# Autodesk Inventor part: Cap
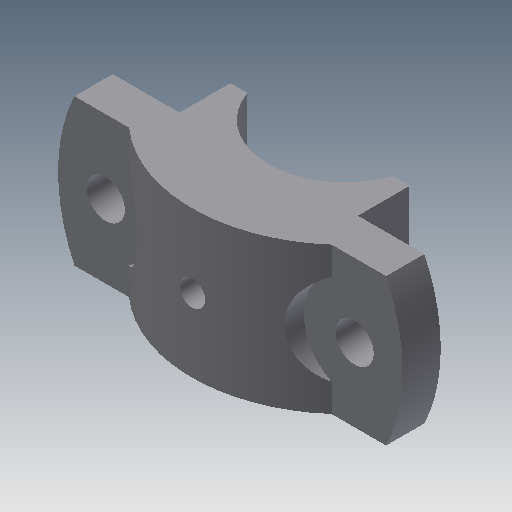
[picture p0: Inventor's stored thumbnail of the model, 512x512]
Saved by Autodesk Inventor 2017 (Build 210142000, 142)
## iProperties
Created: 2009-04
Part Number: Cap
Document SubType Name: Modeling
Designer: Sham
Density: 1 g/cm^3
Material: Generic
Appearance: Default
Author: Sham
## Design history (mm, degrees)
sketch "Sketch1"
  geometry: L1 (-48.857, 23)-(48.857, 23); L2 (48.857, -23)-(-48.857, -23); A1 r 54 centre (0, 0) between (-48.857, 23) and (-48.857, -23); A2 r 54 centre (0, 0) between (48.857, -23) and (48.857, 23); 1 further point
  constraints: 4 end point, 4 point on circle, 2 centre point, 2 coincident, 1 horizontal, 1 parallel, 1 other
  dimensions: "d3" = 54 radius of A1; "d4" = 54 radius of A2; "d5" = 46 distance between parallel lines of L2 L1; "d6" = 23 distance from line of point (0, 0) L1
extrude "Extrusion1" new body sketch "Sketch1" distance "d7" = 12; taper "d8" = 0 deg
sketch "Sketch3"
  geometry: L1 (20.906, 0)-(20.906, -16); L2 (76.906, -0.137)-(76.906, -16.137); L3 (20.906, -16)-(26.23, -16); L4 (71.532, -16.137)-(76.906, -16.137); L5 (76.906, -0.137)-(76.857, 12); L6 (97.714, 0)-(0, 0) reference; L7 (76.857, 12)-(80.606, 12); L8 (17.108, 12)-(20.906, 12); L9 (20.906, 12)-(20.906, 0); L10 (0, 12)-(97.714, 12) reference; A1 r 24 centre (48.857, -24) between (71.532, -16.137) and (26.23, -16); A2 r 48 centre (48.857, -24) between (80.606, 12) and (17.108, 12); 3 further points
  constraints: 16 end point, 4 point on circle, 3 parallel, 3 perpendicular, 2 centre point, 2 coincident, 2 vertical alignment, 1 collinear, 1 midpoint, 1 vertical, 2 other
  dimensions: "d17" = 48 diameter of A1; "d18" = 16 distance of L1.start L1.end; "d19" = 56 distance between parallel lines of L2 L1; "d21" = 8 vertical distance of A1.centre L1.end; "d22" = 48 radius of A2; "d23" = 0 distance from line of L6 L1.start; "d38" = 31.74902 distance of L7.end point (48.857, 12); "d39" = 28 distance from line of point (48.857, 12) L5
extrude "Extrusion2" join sketch "Sketch3" stored distance "d24" = 12; taper "d25" = 0 deg
sketch "Sketch4"
  geometry: 2 further points
  dimensions: "d26" = 78 distance of point (39, 0) point (-39, 0)
hole "Hole1" sketch "Sketch4" at (-39, 0), (39, 0) diameter "d28" = 12; stored, may be unused: countersink angle "d32" = 90 deg, drill point angle "d34" = 118 deg; dims "d29" = 6, "d30" = 4, "d31" = 2, "d33" = 8
sketch "Sketch5"
  geometry: L1 (-31.749, -23)-(-31.749, 23) reference; L2 (-31.749, 14.263)-(-31.749, -14.263); C1 r 6 at (-39, 0) reference; A1 r 16 centre (-39, 0) between (-31.749, -14.263) and (-31.749, 14.263)
  constraints: 2 end point, 2 point on circle, 1 centre point, 1 coincident, 1 collinear, 1 point on line
  dimensions: "d35" = 16 radius of A1
extrude "Extrusion3" cut sketch "Sketch5" distance "d36" = 12; taper "d37" = 0 deg
mirror "Mirror2"
workplane "Work Plane4"
sketch "Sketch6"
  geometry: L1 (-31.749, 0)-(31.749, 0) reference; 1 further point
  dimensions: "d40" = 23 distance from line of L1 point (0, 23)
hole "Hole2" sketch "Sketch6" at (0, 23) diameter "d41" = 6; stored, may be unused: countersink angle "d45" = 90 deg, drill point angle "d47" = 118 deg; dims "d42" = 6, "d43" = 8, "d44" = 16, "d46" = 8
body "Solid1"
